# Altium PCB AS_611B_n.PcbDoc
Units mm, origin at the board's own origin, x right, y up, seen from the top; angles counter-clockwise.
Board outline 32 x 30 mm, 4 copper layers (Top Layer, Layer 1, Layer 2, Bottom Layer), stack 0.98 mm thick; 38 components, 30 nets, 225 pads, 183 vias.
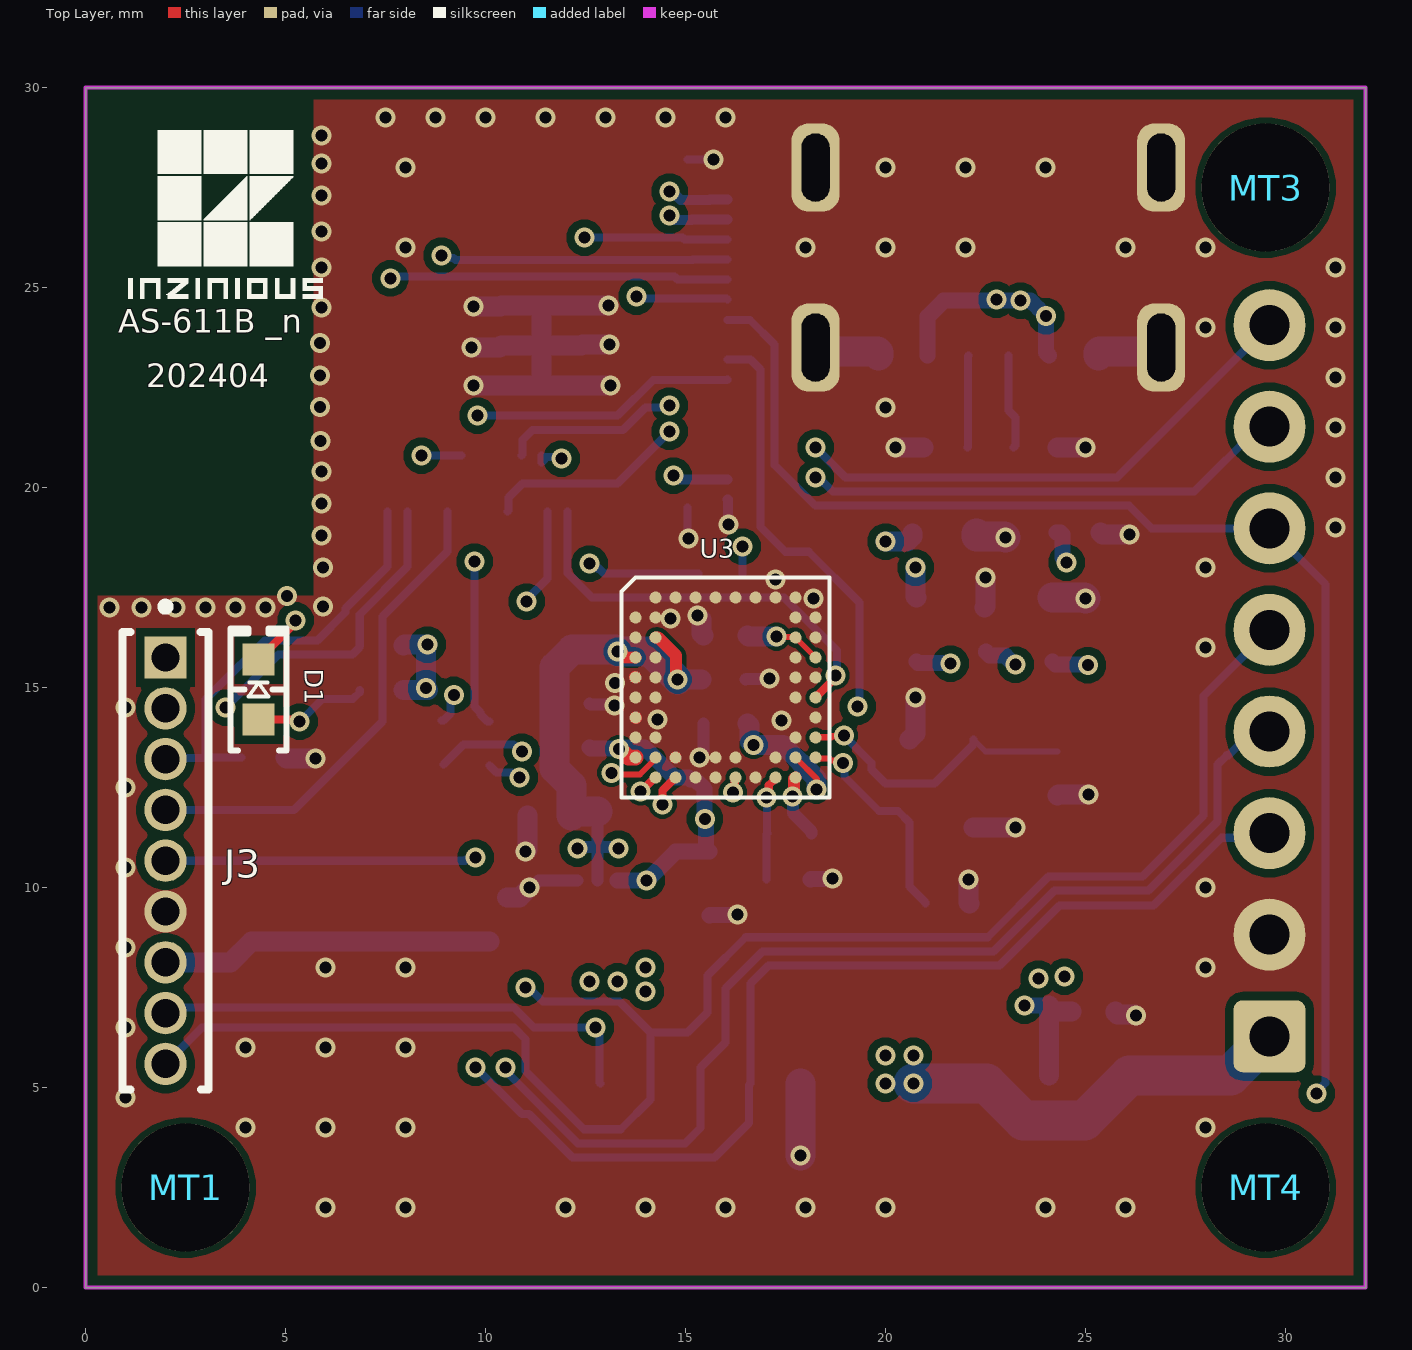
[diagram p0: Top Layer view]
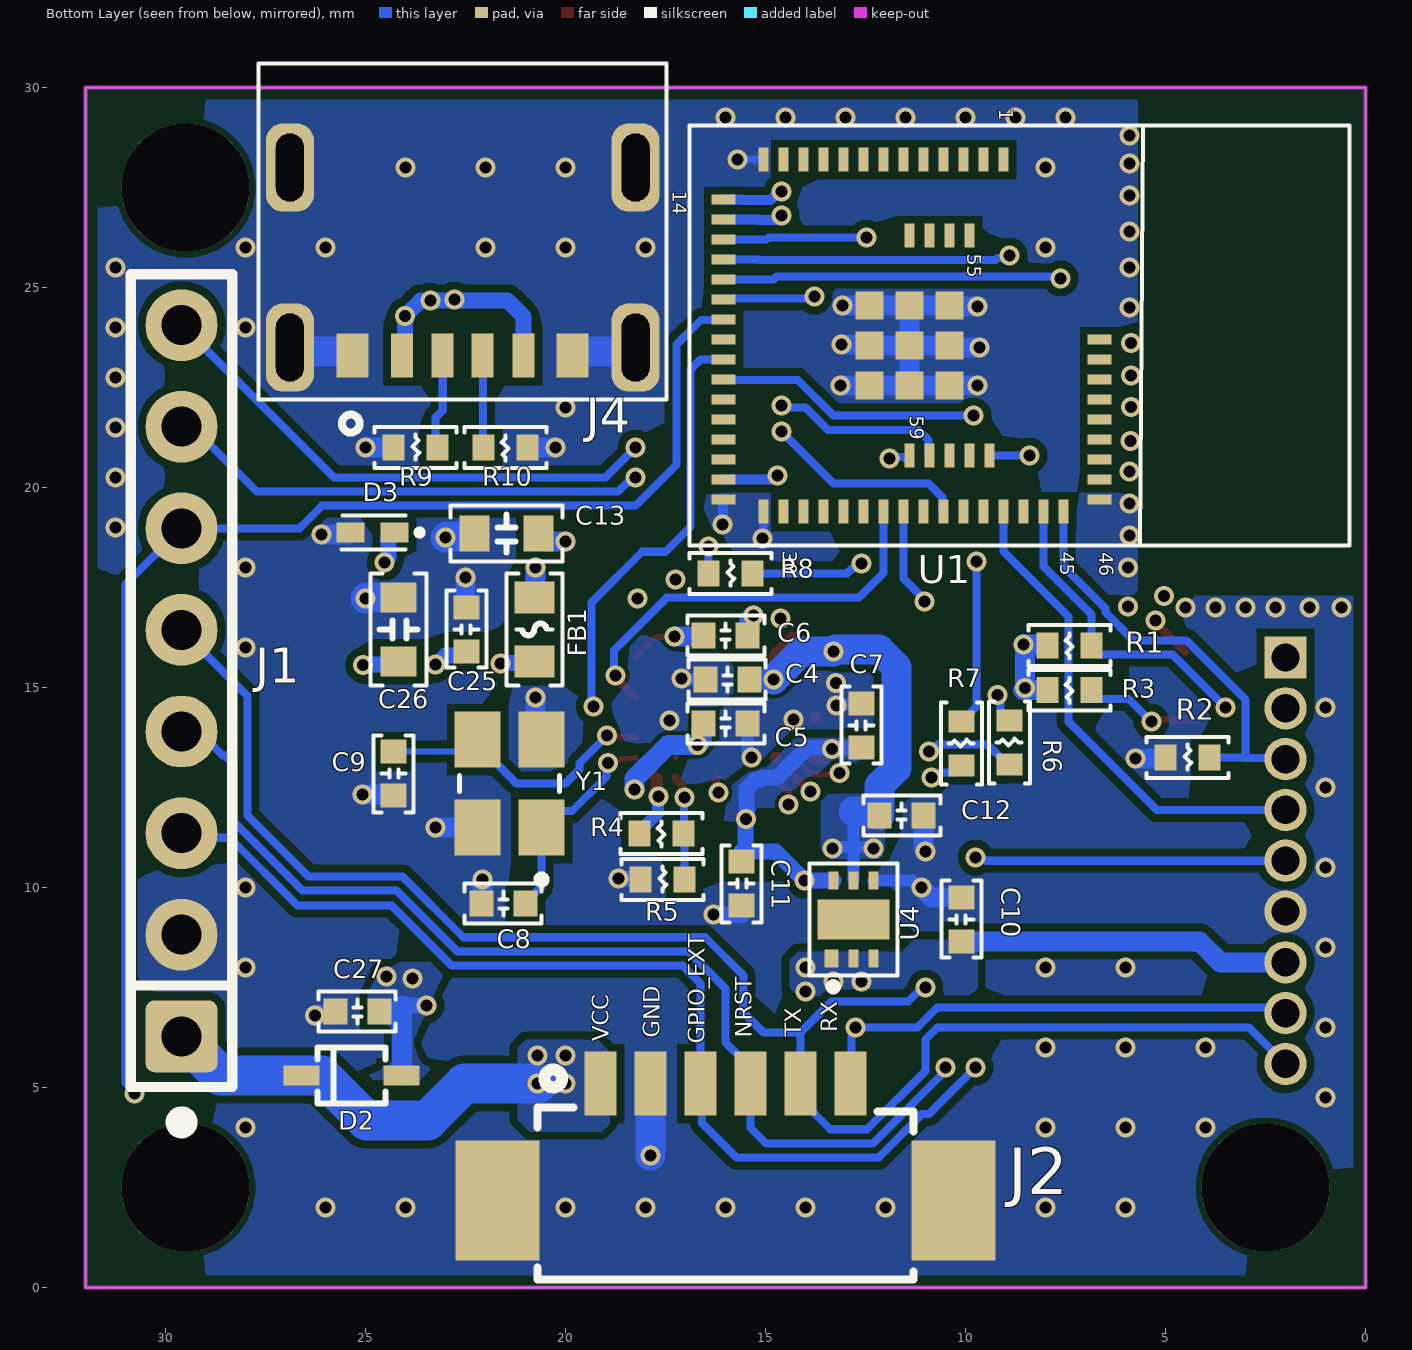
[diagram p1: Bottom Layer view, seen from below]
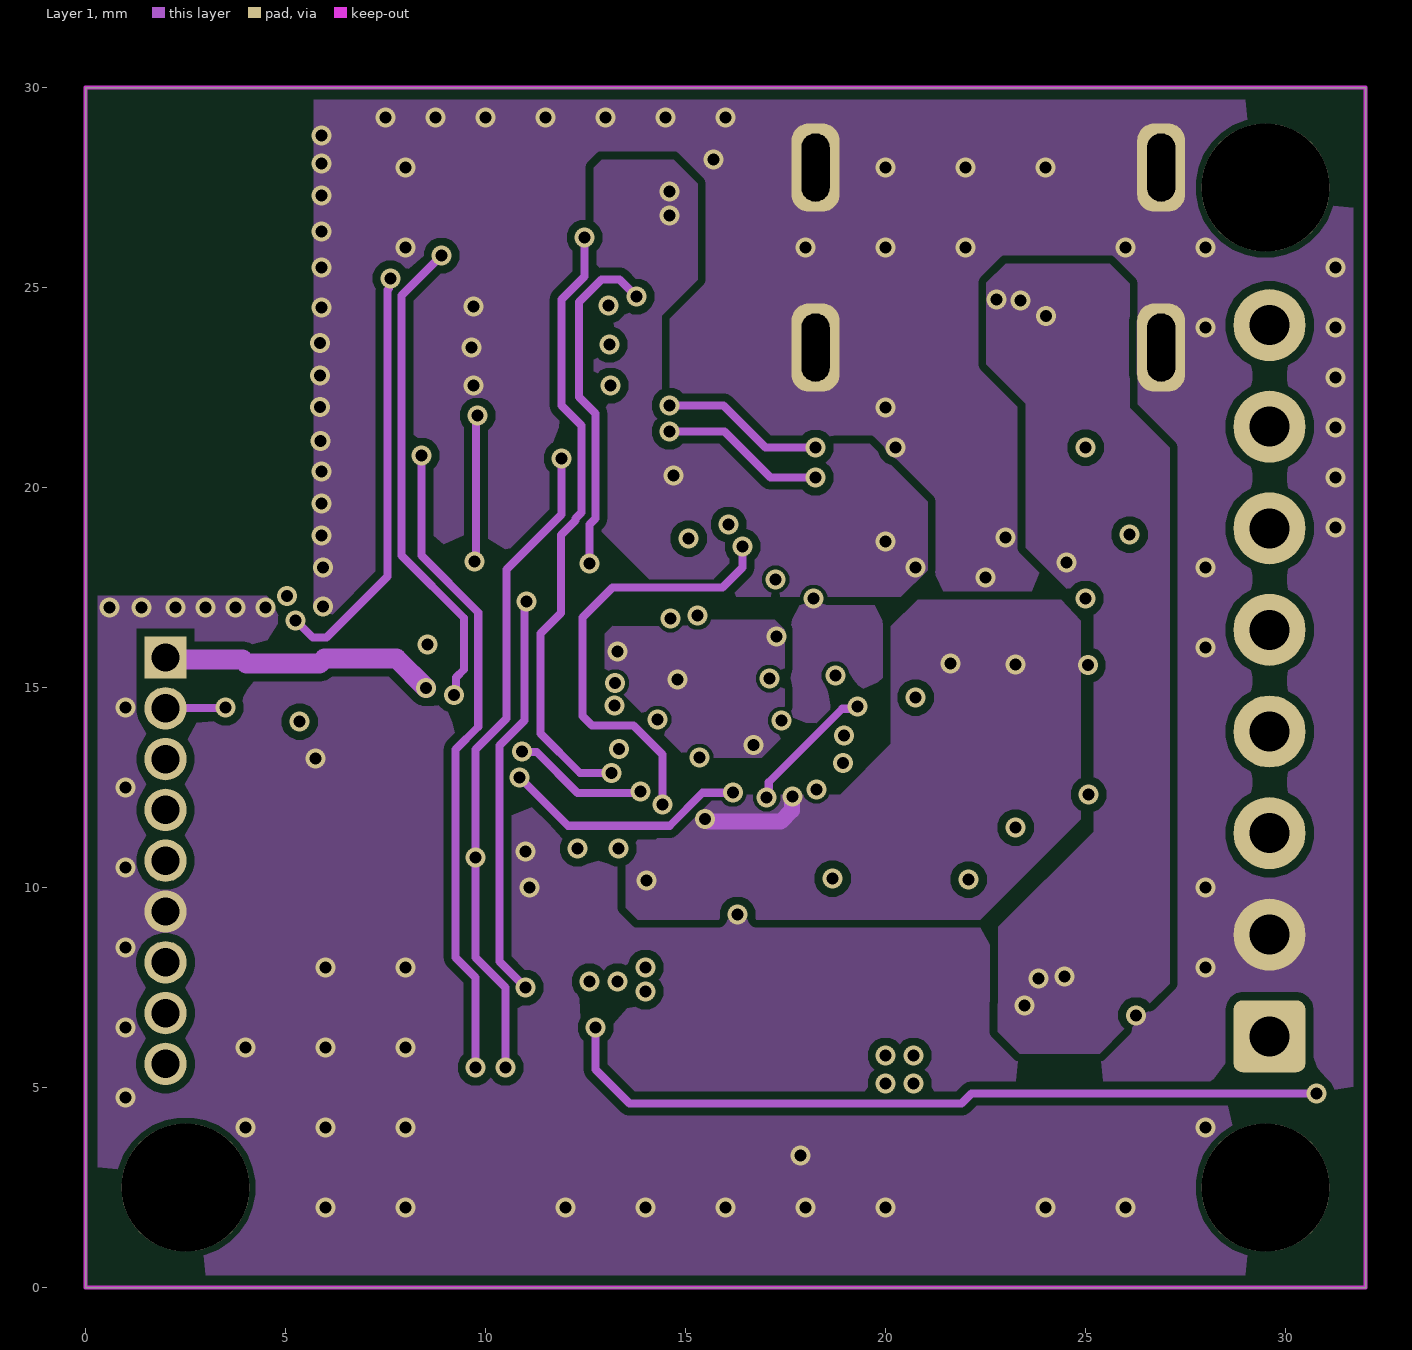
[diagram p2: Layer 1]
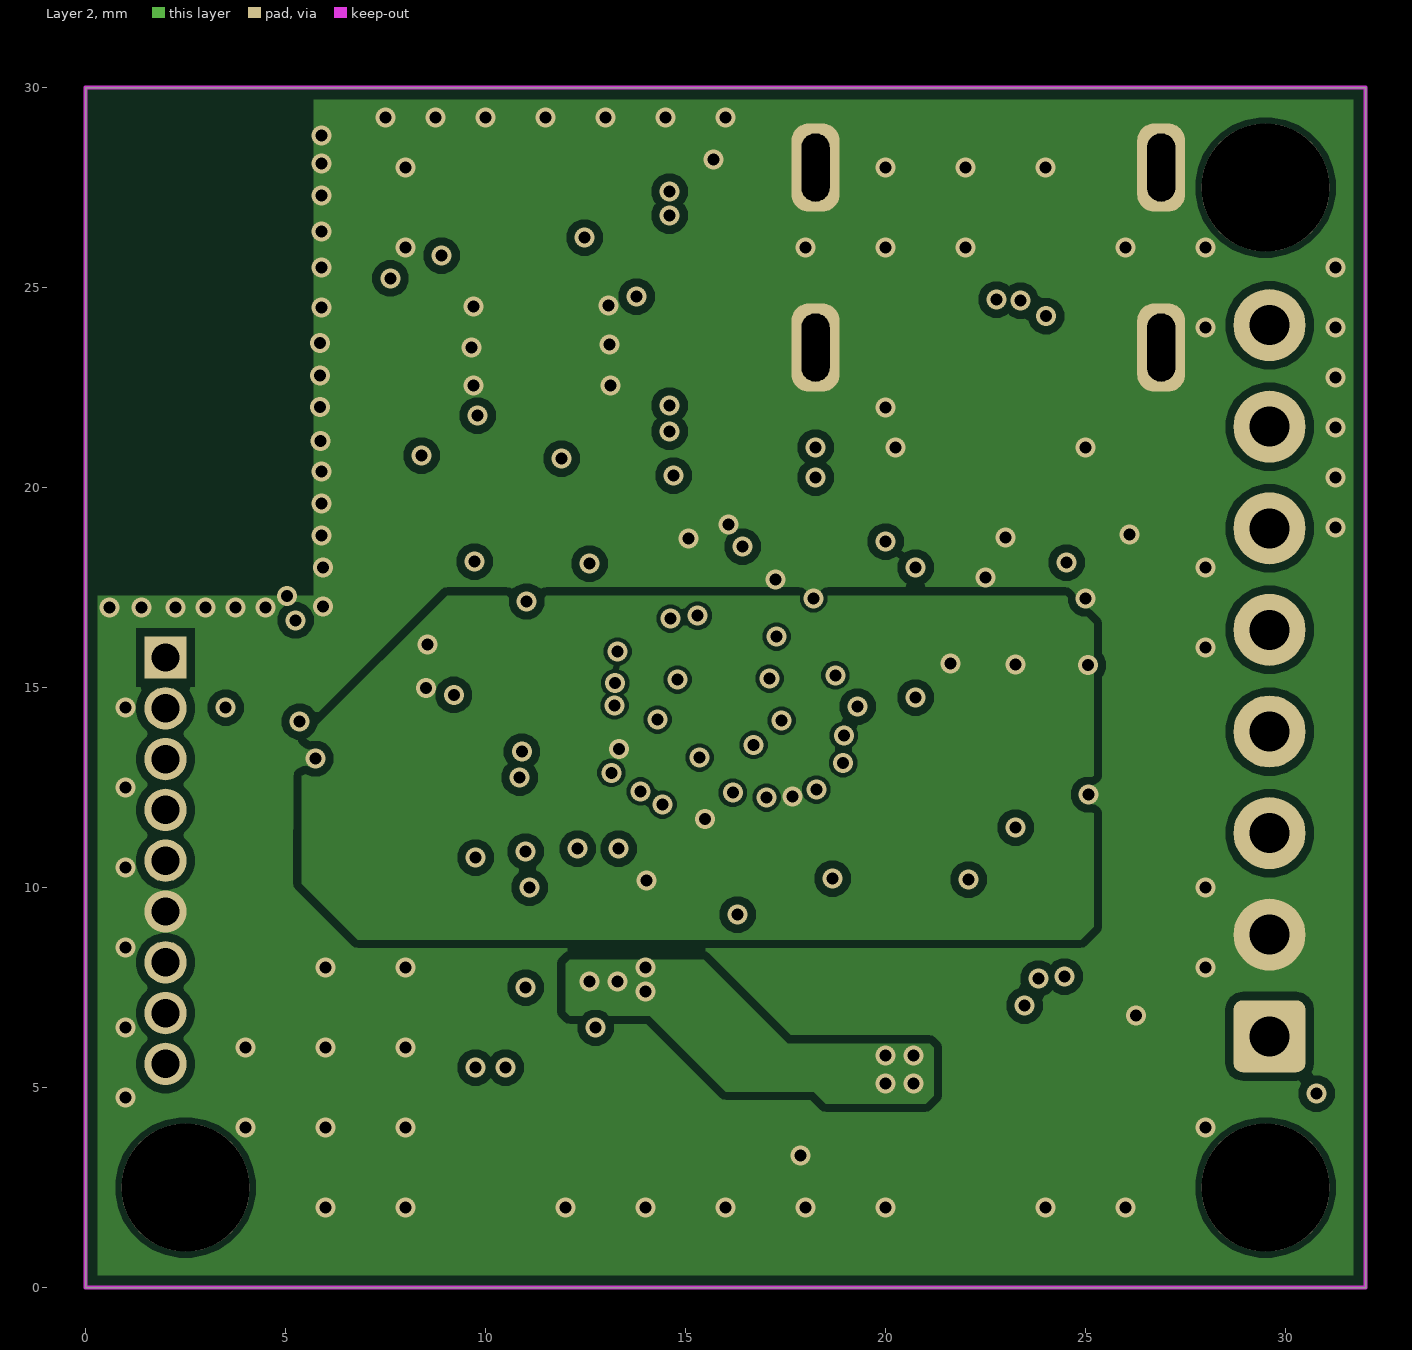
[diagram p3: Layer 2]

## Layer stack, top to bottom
Top Solder: solder mask 0.0102, Solder Resist, Dk 3.5
Top Layer: signal copper 0.0356
Dielectric 2: prepreg 0.0711, PP-006, Dk 4.1
Layer 1: signal copper 0.035
Dielectric 1: dielectric 0.697, FR-4, Dk 4.8
Layer 2: signal copper 0.035
Dielectric 3: prepreg 0.0711, PP-006, Dk 4.1
Bottom Layer: signal copper 0.0356
Bottom Solder: solder mask 0.0102, Solder Resist, Dk 3.5

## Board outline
0,0 0,30 32,30 32,0

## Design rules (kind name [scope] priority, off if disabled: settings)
AssemblyTestPointUsage [All] p1 off:
AssemblyTestpoint [All] p1 off: testpointundercomponent=TRUE minsize=1.016 maxsize=2.54 preferedsize=1.524 minholesize=0 maxholesize=1.016 preferedholesize=0.813 testpointgrid=0.025 usegrid=TRUE gridtolerance=0 allowsidetop=TRUE allowsidebottom=TRUE
BoardOutlineClearance BoardOutlineClearance_1 [OnLayer('Layer 2')] p1 off: gap=0.7 ignorepadtopadclearanceinfootprint=FALSE
BoardOutlineClearance [All] p2: gap=0.3 ignorepadtopadclearanceinfootprint=FALSE
Clearance Clearance_BGA [WithinRoom('BGA')] p1: gap=0.1 ignorepadtopadclearanceinfootprint=TRUE
Clearance [All] p2: gap=0.15 ignorepadtopadclearanceinfootprint=TRUE except(0.2: Arc-Fill Arc-Poly Arc-Region Track-Fill Track-Poly Track-Region SMDPad-Fill SMDPad-Poly SMDPad-Region THPad-Fill THPad-Poly THPad-Region Via-Fill Via-Poly Via-Region Fill-Fill Fill-Poly Fill-Region Poly-Poly Poly-Region Region-Region)
ComponentClearance [All] p1 off: gap=0.254 collisioncheckmode=3 verticalgap=0.254 showdistances=FALSE
DiffPairsRouting [All] p1: maxlimit=0.254 minlimit=0.1 mostfreqgap=0.1 toplayer_minwidth=0.17 toplayer_maxwidth=0.381 toplayer_prefwidth=0.17 midlayer1_minwidth=0.17 midlayer1_maxwidth=0.381 midlayer1_prefwidth=0.17 midlayer2_minwidth=0.17 midlayer2_maxwidth=0.381 midlayer2_prefwidth=0.17 bottomlayer_minwidth=0.17 bottomlayer_maxwidth=0.381 bottomlayer_prefwidth=0.17 maxuncoupledlength=12.7
FabricationTestPointUsage [All] p1 off: valid=0 allowmultiple=FALSE
FabricationTestpoint [All] p1 off: side=3 testpointundercomponent=TRUE minsize=1.016 maxsize=2.54 preferedsize=1.524 minholesize=0 maxholesize=1.016 preferedholesize=0.813 testpointgrid=0.025 allowsidetop=TRUE allowsidebottom=TRUE usegrid=TRUE gridtolerance=0
Height [All] p1 off: minheight=0 maxheight=25.4 prefheight=12.7
HoleSize [All] p1 off: absolutevalues=TRUE maxlimit=2.54 minlimit=0.025 maxpercent=80.000 minpercent=20.000
HoleToHoleClearance [All] p1 off: gap=0.254 allowstackedmicrovias=TRUE
LayerPairs [All] p1 off: enforce=TRUE
MinimumSolderMaskSliver [All] p1 off: minsoldermaskwidth=0.254
NetAntennae [All] p1 off: netantennaetolerance=0
PolygonConnect [All] p1: connectstyle=Direct reliefconductorwidth=0.254 reliefentries=4 polygonreliefangle="90 Angle" airgapwidth=0.254
RoomDefinition BGA [False] p1: confinementstyle=ConfineIn formatcopy=TRUE lockcomponents=FALSE outline 12.981,17.845 19,17.845 19,11.968 12.981,11.968
RoutingVias [All] p1: holewidth=0.711 width=1.27 viastyle="Through Hole" minholewidth=0.711 minwidth=1.27 maxholewidth=0.711 maxwidth=1.27 useviatemplates=TRUE viatemplateguid#1={830B9830-3F13-4738-AC1B-C66D827C6D3A} viatemplatename#1=v50h30m0mx0
SilkToSilkClearance [All] p1 off: silktosilkclearance=0.254
SilkToSolderMaskClearance [IsPad] p1 off: minsilkscreentomaskgap=0.254 clearancetoexposedcopper=TRUE
SolderMaskExpansion [All] p1: expansion=0.102 istentingtop=FALSE
Width [All] p1: maxlimit=3 minlimit=0.15 preferedwidth=0.15
16 further rules are at their usual default settings.

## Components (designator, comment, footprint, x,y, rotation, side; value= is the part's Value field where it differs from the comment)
C4 "1uF" "CAP 0402/1005" 15.95,15.2 r0 bottom
C5 "1uF" "CAP 0402/1005" 16,14.1 r180 bottom
C6 "1uF" "CAP 0402/1005" 16,16.3 r180 bottom
C7 "1uF" "CAP 0402/1005" 12.6,14.05 r90 bottom
C8 "8pF" "CAP 0402/1005" 21.55,9.6 r0 bottom
C9 "8pF" "CAP 0402/1005" 24.3,12.85 r270 bottom
C10 "CAP NP" "CAP 0402/1005" 10.1,9.2 r90 bottom value=1uF
C11 "CAP NP" "CAP 0402/1005" 15.6,10.1 r270 bottom value=1uF
C12 "CAP NP" "CAP 0402/1005" 11.6,11.8 r180 bottom value=1uF
C13 "4.7uF/6.3V/X5R" "CAP 0603/1608" 21.475,18.85 r0 bottom
C25 "0.1uF" "CAP 0402/1005" 22.475,16.45 r90 bottom
C26 "10uF/10V/X7R" "CAP 0603/1608" 24.175,16.45 r270 bottom
C27 "CAP NP" "CAP 0402/1005" 25.2,6.9 r0 bottom value=1uF
D1 "GREEN" "LED 0603/1608 RED -21" 4.325,14.95 r90 top
D2 "DIODE_POWER_0" "SOD-323 - 21" 25.35,5.3 r0 bottom value=BAT760-7
D3 "DIODE BI-DIR TRIG" SOD523 24.825,18.875 r180 bottom value=LESD5D5.0CT1G
FB1 "BLM18AG121SN1D" "FER 0603/1608" 20.775,16.45 r270 bottom
J1 "EXT_IO1/2.54mm" "Pin Header 1x8 TH Pitch 2.54mm" 29.6,6.28 r90 bottom locked
J2 "EXT_IO2/12505wr-06" 12505WR-06/53261-0671 16,5.1 r180 bottom locked
J3 "Debug/1.27mm" "PIN HEADER 1X9 TH 1.27mm" 2,10.671 r270 top
J4 "TYPE-C-31-M-17" CON/USB-C/6P-1 22.57,23.5 r0 bottom locked
MT1 "MOUNT HOLE" "MT-3 /HOLE" 2.5,2.5 r0 top locked
MT3 "MOUNT HOLE" "MT-3 /HOLE" 29.5,27.5 r0 top locked
MT4 "MOUNT HOLE" "MT-3 /HOLE" 29.5,2.5 r0 top locked
R1 "RESISTOR/SM" "RES 0402/1005" 7.4,16.05 r180 bottom value=10K
R2 "RESISTOR/SM" "RES 0402/1005" 4.45,13.25 r0 bottom value=10K
R3 "220R" "RES 0402/1005" 7.405,14.933 r180 bottom
R4 "DNI" "RES 0402/1005" 17.6,11.35 r180 bottom
R5 "DNI" "RES 0402/1005" 17.575,10.2 r0 bottom
R6 "33R" "RES 0402/1005" 8.9,13.625 r270 bottom
R7 "33R" "RES 0402/1005" 10.1,13.6 r270 bottom
R8 "33R" "RES 0402/1005" 15.875,17.85 r0 bottom
R9 "5.1K" "RES 0402/1005" 23.75,21 r0 bottom
R10 "5.1K" "RES 0402/1005" 21.5,21 r180 bottom
U1 "NU-BW4001" nu40 11.4,23.55 r270 bottom locked value=nRF52840-QIAA
U3 "A121" A111 16,15 r0 top locked
U4 "VRD1833MLX" "LLP-6 / L2.0-W1.8-P0.50-BL-EP" 12.825,9.2 r180 bottom
Y1 "24MHz" XTAL_3225 21.4,12.6 r90 bottom

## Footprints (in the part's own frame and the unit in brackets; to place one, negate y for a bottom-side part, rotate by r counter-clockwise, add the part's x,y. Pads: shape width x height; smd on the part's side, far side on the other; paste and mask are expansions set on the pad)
12505WR-06/53261-0671 [mm]
  rect 0.8x1.6 smd: 1(-3.125,0) 2(-1.875,0) 3(-0.625,0) 4(0.625,0) 5(1.875,0) 6(3.125,0)
  rect 2.1x3 smd: H(-5.7,-2.925) H(5.7,-2.925)
  silkscreen extent -4.7,-4.9 4.7,0.35, body extent -6.39,-4.75 6.26,0.45, height 3.4
A111 [mm]
  round 0.3 smd: A2(-1.75,2.25) A3(-1.25,2.25) A4(-0.75,2.25) A5(-0.25,2.25) A6(0.25,2.25) A7(0.75,2.25) A8(1.25,2.25) A9(1.75,2.25) B1(-2.25,1.75) B2(-1.75,1.75) B9(1.75,1.75) B10(2.25,1.75) C1(-2.25,1.25) C2(-1.75,1.25) C9(1.75,1.25) C10(2.25,1.25) D1(-2.25,0.75) D2(-1.75,0.75) D9(1.75,0.75) D10(2.25,0.75) E1(-2.25,0.25) E2(-1.75,0.25) E9(1.75,0.25) E10(2.25,0.25) F1(-2.25,-0.25) F2(-1.75,-0.25) F9(1.75,-0.25) F10(2.25,-0.25) G1(-2.25,-0.75) G10(2.25,-0.75) H1(-2.25,-1.25) H2(-1.75,-1.25) H9(1.75,-1.25) H10(2.25,-1.25) J1(-2.25,-1.75) J2(-1.75,-1.75) J3(-1.25,-1.75) J5(-0.25,-1.75) J6(0.25,-1.75) J8(1.25,-1.75) J9(1.75,-1.75) J10(2.25,-1.75) K2(-1.75,-2.25) K3(-1.25,-2.25) K4(-0.75,-2.25) K5(-0.25,-2.25) K6(0.25,-2.25) K7(0.75,-2.25) K8(1.25,-2.25) K9(1.75,-2.25)
  silkscreen extent -2.6,-2.75 2.6,2.75, body extent -2.61,-2.75 2.63,2.75, height 0.9
"CAP 0402/1005" [mm] "Chip Capacitor, 2-Leads, Body 1.02x0.51mm, IPC Medium Density"
  rect 0.6x0.65 smd: 1(-0.55,0) 2(0.55,0)
  silkscreen extent -0.95,-0.5 0.97,0.5, body extent -0.5,-0.26 0.5,0.26, height 0.52
"CAP 0603/1608" [mm] "Chip Capacitor, 2-Leads, Body 1.60x0.80mm, IPC Medium Density"
  rect 0.75x0.9 smd: 1(-0.8,0) 2(0.8,0)
  silkscreen extent -1.4,-0.7 1.4,0.7, body extent -0.8,-0.41 0.8,0.41, height 0.82
CON/USB-C/6P-1 [mm]
  rect 0.55x1.1 smd: A5(-0.5,0.2) A9(1.52,0.2) B5(0.5,0.2) B9(-1.52,0.2)
  rect 0.8x1.1 smd: A12(2.75,0.2) B12(-2.75,0.2)
  rrect70% 1.2x2.2 hole 0.7 slot 1.7 at 90 deg: MP(-4.32,-4.5) MP(-4.32,0) MP(4.32,-4.5) MP(4.32,0)
  silkscreen extent -5.1,-7.1 5.1,2.12, body extent -4.47,-6.7 4.47,0.2, height 3.26
"FER 0603/1608" [mm] "Chip Ferrite, 2-Leads, Body 1.60x0.80mm, IPC Medium Density"
  rect 0.8x1 smd: 1(-0.8,0) 2(0.8,0)
  silkscreen extent -1.4,-0.7 1.4,0.7, body extent -0.8,-0.41 0.8,0.41, height 0.82
"LED 0603/1608 RED -21" [mm] "Chip Diode, 2-Leads, Body 1.60x0.80mm, IPC Medium Density"
  rect 0.8x0.8 smd: 1(0.75,0) 2(-0.75,0)
  silkscreen extent -1.52,-0.7 1.52,0.7, body extent -0.8,-0.4 0.8,0.4, height 0.53
"LLP-6 / L2.0-W1.8-P0.50-BL-EP" [mm]
  rect 0.35x0.45 smd paste+0 mask+0.051: 1(-0.525,-0.975)
  rect 0.25x0.45 smd paste+0 mask+0.051: 2(0.025,-0.975) 3(0.525,-0.975) 4(0.525,0.975) 5(0.025,0.975) 6(-0.475,0.975)
  rect 1.8x1 smd paste+0 mask+0.051: 7(0.025,0)
  silkscreen extent -1.07,-1.74 1.12,1.4, body extent -0.9,-1 0.9,1, height 0.6
"MT-3 /HOLE" [mm] "Mount Hole 4mm"
  round 3.2 hole 3.2 unplated mask+0: 1(0,0)
nu40 [mm]
  rect 0.6x0.25 smd mask+0.05: 1(-4.65,2.35) 2(-4.65,1.85) 3(-4.65,1.35) 4(-4.65,0.85) 5(-4.65,0.35) 6(-4.65,-0.15) 7(-4.65,-0.65) 8(-4.65,-1.15) 9(-4.65,-1.65) 10(-4.65,-2.15) 11(-4.65,-2.65) 12(-4.65,-3.15) 13(-4.65,-3.65) 30(4.15,-3.65) 31(4.15,-3.15) 32(4.15,-2.65) 33(4.15,-2.15) 34(4.15,-1.65) 35(4.15,-1.15) 36(4.15,-0.65) 37(4.15,-0.15) 38(4.15,0.35) 39(4.15,0.85) 40(4.15,1.35) 41(4.15,1.85) 42(4.15,2.35) 43(4.15,2.85) 44(4.15,3.35) 45(4.15,3.85) 55(-2.75,1.5) 56(-2.75,1) 57(-2.75,0.5) 58(-2.75,0) 59(2.75,0) 60(2.75,0.5) 61(2.75,1) 62(2.75,1.5) 63(2.75,2)
  rect 0.25x0.6 smd mask+0.05: 14(-3.65,-4.65) 15(-3.15,-4.65) 16(-2.65,-4.65) 17(-2.15,-4.65) 18(-1.65,-4.65) 19(-1.15,-4.65) 20(-0.65,-4.65) 21(-0.15,-4.65) 22(0.35,-4.65) 23(0.85,-4.65) 24(1.35,-4.65) 25(1.85,-4.65) 26(2.35,-4.65) 27(2.85,-4.65) 28(3.35,-4.65) 29(3.85,-4.65) 46(3.85,4.75) 47(3.35,4.75) 48(2.85,4.75) 49(2.35,4.75) 50(1.85,4.75) 51(1.35,4.75) 52(0.85,4.75) 53(0.35,4.75) 54(-0.15,4.75)
  rect 0.7x0.7 smd paste-2539.97 mask+0: 64(-1,1) 65(0,1) 66(1,1) 67(-1,0) 68(0,0) 69(1,0) 70(-1,-1) 71(0,-1) 72(1,-1)
  silkscreen extent -5.5,-5.5 5,11, body extent -5.51,-5.5 5,11.01, height 2.4
"Pin Header 1x8 TH Pitch 2.54mm" [mm] "PinHeader 1x8 TH Pitch 2.54mm"
  rrect25% 1.8x1.8 hole 1: 1(0,0)
  round 1.8 hole 1: 2(2.54,0) 3(5.08,0) 4(7.62,0) 5(10.16,0) 6(12.7,0) 7(15.24,0) 8(17.78,0)
  silkscreen extent -2.3,-1.27 19.05,1.27, body extent -1.27,-1.27 19.05,1.27, height 9.5
"PIN HEADER 1X9 TH 1.27mm" [mm]
  rect 1.06x1.06 hole 0.71: 1(-5.08,0)
  round 1.06 hole 0.71: 2(-3.81,0) 3(-2.54,0) 4(-1.27,0) 5(0,0) 6(1.27,0) 7(2.54,0) 8(3.81,0) 9(5.08,0)
  silkscreen extent -6.45,-1.08 5.71,1.08, body extent -5.71,-1.08 5.71,1.08, height 3.91
"RES 0402/1005" [mm] "Chip Resistor, 2-Leads, Body 1.0x0.5mm, IPC Medium Density"
  rect 0.55x0.65 smd: 1(-0.55,0) 2(0.55,0)
  silkscreen extent -1.02,-0.51 1.02,0.51, body extent -0.5,-0.25 0.5,0.25, height 0.35
SOD523 [mm]
  rect 0.7x0.5 smd: 1(0.55,0) 2(-0.55,0)
  silkscreen extent -0.77,-0.43 1.22,0.43, body extent -0.77,-0.4 0.83,0.4, height 0.65
"SOD-323 - 21" [mm]
  rect 0.9x0.5 smd: 1(1.25,0) 2(-1.25,0)
  silkscreen extent -0.85,-0.7 0.85,0.7, body extent -1.34,-0.66 1.34,0.64, height 1.15
XTAL_3225 [mm]
  rect 1.4x1.15 smd: 1(-1.1,-0.8) 2(1.1,-0.8) 3(1.1,0.8) 4(-1.1,0.8)
  silkscreen extent -2.5,-1.25 0.2,1.25, body extent -1.6,-1.25 1.6,1.25, height 1

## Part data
C4 C5 C6 C7 C8 C9: library part "CAP NP"
C13 C25: library part C0603-4µ7-6.3V-X7R, "Capacitor, X7R, ±10%"
C26: library part Cap, "MLCC"
D1: library part LED
FB1: library part FB0402-120R@100M-500mA, "Ferrite Bead, 120 Ohm @ 100MHz, 500mA, 250 mOhm Max", Manufacturer=Murata, Manufacturer Part Number=BLM15AG121SN1D, Part number IPS=00000009954, Supplier Part Number 1=490-1005-1-ND
J1: library part "HEADER 8"
J2: library part "HEADER 6"
J3: library part "Header 9", "Header, 9-Pin"
J4: library part CON/USB-C/6P, "6P C-type Connector"
MT1 MT3 MT4: library part "Mount Bolt"
R3 R4 R5 R6 R7 R8 R9 R10: library part RESISTOR/SM
U1: library part nu40_1, "BLE Module", Manufacturer="Nordic Semiconductor", Manufacturer Part Number=nRF52840-QIAAF0, Part number IPS=N.A.
Y1: library part CRYSTAL13

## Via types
v1: diameter 0.5, hole 0.3, Top Layer to Bottom Layer, tented both sides, 183 vias

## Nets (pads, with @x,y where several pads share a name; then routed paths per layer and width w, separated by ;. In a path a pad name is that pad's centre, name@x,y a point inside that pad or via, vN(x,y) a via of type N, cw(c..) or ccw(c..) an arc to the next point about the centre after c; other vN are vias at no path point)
ENABLE: U1.36 U3.F10 | length 10.5
  Top Layer w0.203: U3.F10 18.25,14.753 18.747,15.25 v1(18.747,15.305)
  Bottom Layer w0.203: U1.36 12.05,17.864 12.664,17.25 17.466,17.25 18.788,15.927 18.788,15.347 v1(18.747,15.305)
GND: C4.2 C5.2 C6.2 C7.2 C8.2 C9.2 C10.2 C11.2 C12.2 C13.2 C25.2 C26.1 C27.2 D3.2 J1.2 J2.2 J2.H J3.6 J4.A12 J4.B12 J4.MP R2.2 R5.2 R9.2 R10.2 U1.13 U1.29 U1.30 U1.46 U1.64 U1.65 U1.66 U1.67 U1.68 U1.69 U1.70 U1.71 U1.72 U3.A2 U3.A3 U3.A4 U3.A5 U3.A6 U3.A7 U3.A8 U3.A9 U3.B1 U3.B2 U3.B9 U3.B10 U3.C1 U3.C10 U3.D2 U3.D9 U3.E1 U3.E2 U3.E9 U3.E10 U3.F1 U3.F2 U3.F9 U3.G1 U3.G10 U3.H1 U3.H2 U3.H9 U3.J3 U3.J5 U3.J6 U3.J8 U3.K4 U3.K5 U3.K7 U4.4 Y1.2 Y1.4 | length 36.2
  Top Layer w0.3: v1(13.242,15.11) v1@13.262,15.11 ; U3.E1@13.738,15.262 U3.E1 ; U3.G1 U3.G1@13.762,14.238 ; v1@14.262,14.238 v1(14.3,14.2) ; v1@15.312,13.212 v1(15.35,13.25) ; v1(17.4,14.175) v1@17.438,14.137 ; v1(18.2,17.225) 18.2,17.171 v1@18.25,17.121
  Bottom Layer w0.2: U1.30@15.05,19.499 15.056,19.493 15.056,18.744 v1(15.075,18.725) ; U1.13 v1(15.7,28.2)
  Bottom Layer w0.25: U1.29 16.063,19.7 16.063,19.087 v1(16.076,19.074)
  Bottom Layer w0.3: v1(11.1,10) 11.154,10 11.329,10.175 U4.4 ; C7.2 12.624,14.576 13.201,14.576 v1(13.225,14.552) ; v1(15.35,13.25) 15.35,13.304 15.45,13.404 C5.2 ; C4.2 16.512,15.212 17.087,15.212 v1(17.1,15.225)
  Bottom Layer w0.4: C11.2@15.6,9.3 15.613,9.313 16.288,9.313 v1(16.3,9.325) ; R5.2 18.137,10.212 18.663,10.212 v1(18.675,10.225)
  Bottom Layer w0.5: R2.2 5.025,13.225 v1(5.75,13.225) ; v1(9.65,23.5) 10.35,23.5 U1.65 U1.68 ; v1(9.7,22.55) U1.66 U1.69 ; v1(9.7,24.525) 10.375,24.525 U1.64 U1.67 ; 10.543,9.75 10.75,9.75 10.85,9.75 v1(11.1,10) ; v1(11,10.9) 11.05,10.95 C12.2 ; v1(13.075,24.55) U1.70 U1.67 ; v1(13.1,23.575) 12.425,23.575 U1.71 U1.68 ; v1(13.125,22.55) U1.72 U1.69 ; v1(15.304,16.796) 15.4,16.7 15.4,16.35 C6.2 ; v1(20.25,21) R10.2 ; Y1.2 20.75,13.85 v1(20.75,14.75) ; v1(22.075,10.2) 22.075,9.625 C8.2 ; Y1.4 v1(23.25,11.5) ; C25.2 22.5,17.025 v1(22.5,17.75) ; C9.2 24.325,12.325 v1(25.075,12.325) ; R9.2 v1(25,21) ; D3.2 25.428,18.822 v1(26.102,18.822) ; C27.2 25.75,6.875 25.8,6.825 26.242,6.825 v1(26.26,6.807) ; U1.69 U1.68 ; U1.68 U1.67
  Bottom Layer w0.75: v1(17.875,3.3) J2.2 ; J4.MP@18.25,23.5 18.35,23.4 19.795,23.4 19.82,23.375 J4.B12 ; C13.2 22.275,18.775 22.975,18.775 v1(23,18.75) ; C26.1 24.975,17.25 v1(25,17.225) ; J4.A12 25.32,23.375 25.345,23.4 26.79,23.4 J4.MP@26.89,23.5
  other v1: 6,2 8,2 12,2 14,2 16,2 18,2 20,2 24,2 26,2 4,4 6,4 8,4 28,4 1,4.75 4,5.998 6,5.998 8,5.998 1,6.5 6,8 8,8 28,8 1,8.5 28,10 1,10.5 1,12.5 1,14.5 28,16 14.625,16.725 0.6,17 1.4,17 2.25,17 3,17 3.75,17 4.5,17 5.936,17.025 5.032,17.294 17.25,17.702 5.937,18.006 28,18 5.9,18.8 31.25,19 5.9,19.6 31.25,20.25 5.9,20.4 5.874,21.16 31.25,21.5 20,22 5.865,22.017 31.25,22.75 5.857,22.801 5.865,23.618 28,24 31.25,24 5.9,24.5 5.9,25.5 31.25,25.5 8,26 18,26 20,26 22,26 26,26 28,26 5.9,26.4 5.9,27.3 8,28 20,28 22,28 24,28 5.9,28.1 5.9,28.8 7.5,29.25 8.75,29.25 10,29.25 11.5,29.25 13,29.25 14.5,29.25 16,29.25
GPIO_EXT: J1.3 J2.3 U1.63 | length 43.5
  Layer 1 w0.203: v1(8.4,20.8) 8.4,18.297 9.819,16.879 9.819,14.018 9.248,13.448 9.248,8.253 9.75,7.751 v1(9.75,5.5)
  Bottom Layer w0.203: v1(8.4,20.8) U1.63 ; v1(9.75,5.5) 10.913,4.337 11.084,4.337 12.17,3.25 15.725,3.25 16.589,4.114 16.589,5.064 J2.3 16.625,7.6 17.075,8.05 22.849,8.05 24.349,9.55 26.7,9.55 28.395,11.245 29.485,11.245 J1.3
INTERRUPT: R4.2 R5.1 U1.22 U3.K8 | length 16.8
  Top Layer w0.203: v1(17.025,12.25) 17.082,12.307 17.082,12.556 17.25,12.724 U3.K8
  Layer 1 w0.203: v1(17.025,12.25) 17.082,12.307 17.082,12.632 18.918,14.468 19.243,14.468 v1(19.3,14.525)
  Bottom Layer w0.203: U1.22 16.625,23.2 16.873,22.952 16.873,19.021 17.5,18.394 18.081,18.394 19.348,17.127 19.348,14.573 v1(19.3,14.525) ; R5.1 17.025,11.325 R4.2 17.037,11.363 17.037,12.238 v1(17.025,12.25)
LED: D1.1 U1.18 | length 20.2
  Top Layer w0.2: D1.1@4.513,15.888 5.25,16.625 v1(5.25,16.681)
  Layer 1 w0.2: v1(5.25,16.681) 5.681,16.25 6.025,16.25 7.55,17.775 7.55,24.933 7.593,24.975 7.593,25.2 v1(7.621,25.229)
  Bottom Layer w0.2: v1(7.621,25.229) 7.668,25.275 14.725,25.275 14.8,25.2 U1.18
NetC8_1: C8.1 U3.J10 Y1.1 | length 5.4
  Top Layer w0.152: U3.J10 18.275,13.225 18.6,13.225 18.649,13.177 18.874,13.177 v1(18.941,13.11)
  Bottom Layer w0.2: v1(18.941,13.11) 18.979,13.072 18.979,12.771 19.842,11.908 20.317,11.908 20.6,11.625 20.6,10.025 21,9.625 C8.1
NetC9_1: C9.1 U3.H10 Y1.3 | length 7.3
  Top Layer w0.152: U3.H10 18.258,13.758 18.642,13.758 18.667,13.783 18.942,13.783 v1(18.959,13.799)
  Bottom Layer w0.152: Y1.3 22.5,13.4 C9.1
  Bottom Layer w0.2: v1(18.959,13.799) 19.65,13.108 19.65,12.95 20,12.6 21.225,12.6 22.2,13.575 Y1.3
NetC27_1: C27.1 D2.2 D3.1 J4.A9 J4.B9 | length 9
  Bottom Layer w0.4: J4.B9 21.05,24.275 21.45,24.675 23.625,24.675 23.824,24.476 v1(24.015,24.285) 24.015,23.375 J4.A9 ; v1(23.475,7.05) 24.1,7.05 ; D3.1 24.375,18.875 24.425,18.825 24.425,18.252 24.525,18.152 v1(24.525,18.125)
  Bottom Layer w0.5: D2.2@24.085,5.3 24.085,7.05 ; 24.189,6.9 C27.1
  other v1: 23.825,7.725 24.475,7.775 23.375,24.675 22.775,24.7
NetD1_2: D1.2 R3.2 | length 2.9
  Top Layer w0.203: D1.2 5.3,14.2 v1(5.355,14.145)
  Bottom Layer w0.203: v1(5.355,14.145) 5.919,14.71 6.682,14.71 6.855,14.883 R3.2
NetJ4_A5: J4.A5 R10.1 | length 2.3
  Bottom Layer w0.203: R10.1 22.06,21.01 22.06,23.29 J4.A5
NetJ4_B5: J4.B5 R9.1 | length 2.4
  Bottom Layer w0.203: J4.B5 23.07,21.93 23.25,21.75 23.25,21.05 R9.1
NetR6_2: R6.2 U3.K2 | length 6.2
  Top Layer w0.203: v1(13.875,12.402) 13.888,12.402 14.237,12.75 U3.K2
  Layer 1 w0.203: v1(10.907,13.398) 10.917,13.388 11.28,13.388 12.302,12.366 12.908,12.366 13.839,12.366 v1(13.875,12.402)
  Bottom Layer w0.203: R6.2@8.95,13.075 9.452,13.577 10.698,13.577 10.877,13.398 v1(10.907,13.398)
NetR7_2: R7.2 U3.K6 | length 7.5
  Top Layer w0.203: v1(16.181,12.369) 16.231,12.42 16.231,12.731 U3.K6
  Layer 1 w0.203: v1(10.855,12.75) 12.059,11.545 14.605,11.545 15.429,12.369 v1(16.181,12.369)
  Bottom Layer w0.2: R7.2 10.275,12.875 10.649,12.875 10.774,12.75 v1(10.855,12.75)
NetR8_2: R8.2 U3.K3 | length 12.6
  Top Layer w0.203: v1(14.425,12.075) 14.425,12.425 U3.K3
  Layer 1 w0.203: v1(14.425,12.075) 14.425,13.325 13.7,14.05 12.659,14.05 12.425,14.284 12.425,16.75 13.175,17.5 15.925,17.5 16.425,18 v1(16.425,18.525)
  Bottom Layer w0.203: R8.2 v1(16.425,18.525)
NRST: J1.4 J2.4 J3.5 U1.59 | length 51.7
  Layer 1 w0.203: v1(10.5,5.5) 10.5,7.501 9.75,8.251 v1(9.75,10.75) 9.75,13.45 10.525,14.225 10.525,17.95 11.9,19.325 v1(11.9,20.725)
  Bottom Layer w0.203: J3.5 9.483,10.671 9.505,10.693 9.693,10.693 v1(9.75,10.75) ; v1(10.5,5.5) 10.5,5.42 12.316,3.603 14.983,3.603 15.375,3.995 15.375,5.5 16,6.125 16,7.474 16.929,8.403 22.703,8.403 24.223,9.923 26.573,9.923 28.3,11.651 28.3,13.075 28.532,13.307 28.575,13.307 29.168,13.9 J1.4 ; U1.59 11.4,20.625 U1.59@11.488,20.713 ; U1.59@11.402,20.798 11.402,20.784 11.423,20.762 11.863,20.762 v1(11.9,20.725)
SPI_CLK: R6.1 U1.17 | length 20.2
  Layer 1 w0.2: v1(8.9,25.8) 7.9,24.8 7.9,18.3 9.467,16.733 9.467,15.456 9.263,15.252 9.263,14.871 v1(9.206,14.814)
  Bottom Layer w0.2: R6.1 8.95,14.175 9.125,14.35 9.125,14.652 9.206,14.732 v1(9.206,14.814) ; v1(8.9,25.8) 8.957,25.743 9.196,25.743 9.246,25.693 15.175,25.693 15.182,25.7 U1.17
SPI_MISO: R8.1 U1.19 | length 13.8
  Layer 1 w0.203: v1(12.6,18.1) 12.6,19.078 12.752,19.229 12.752,21.848 12.336,22.264 12.336,24.639 12.897,25.2 13.35,25.2 v1(13.775,24.775)
  Bottom Layer w0.203: v1(12.6,18.1) 12.68,18.1 12.813,17.968 12.846,17.968 12.964,17.85 R8.1 ; v1(13.775,24.775) 13.827,24.723 16.027,24.723 U1.19
SPI_MOSI: R7.1 U1.23 | length 14.5
  Layer 1 w0.203: v1(9.725,18.15) 9.763,18.187 9.763,21.762 v1(9.8,21.8)
  Bottom Layer w0.203: v1(9.725,18.15) 9.725,14.525 9.877,14.373 9.877,14.323 10.05,14.15 R7.1 ; v1(9.8,21.8) 13.301,21.8 14.193,22.693 16.043,22.693 U1.23
SPI_SS: U1.16 U3.J2 | length 20.4
  Top Layer w0.15: v1(13.147,12.867) 13.187,12.827 13.857,12.827 14.25,13.22 U3.J2
  Layer 1 w0.2: v1(12.475,26.25) 12.475,25.275 11.9,24.7 11.9,22.05 12.4,21.55 12.4,19.375 12.248,19.223 12.248,19.176 11.887,18.814 11.887,16.86 11.377,16.35 11.377,13.848 12.358,12.867 v1(13.147,12.867)
  Bottom Layer w0.2: v1(12.475,26.25) 14.921,26.25 14.971,26.2 U1.16
SWCLK: J3.3 R2.1 U1.45 | length 10.7
  Bottom Layer w0.203: J3.3 2.023,13.234 3.003,13.234 ; R2.1 3.019,13.25 3.003,13.234 ; U1.45 7.55,18.025 6.502,16.976 6.502,16.881 5.801,16.18 4.48,16.18 3.301,15 3.003,14.703 3.003,13.234
SWDIO: J3.2 R1.2 U1.44 | length 9.4
  Layer 1 w0.203: J3.2 2.007,14.488 3.498,14.488 v1(3.505,14.495)
  Bottom Layer w0.203: v1(3.505,14.495) 3.505,14.505 4.827,15.827 6.677,15.827 6.85,16 R1.2 ; R1.2@6.855,16.055 6.855,16.83 8.05,18.025 U1.44
SWO: J3.4 U1.42 | length 12.3
  Bottom Layer w0.203: J3.4 5.216,11.941 7.423,14.148 7.423,16.773 9.05,18.4 U1.42
UART_CTS: J1.8 U1.60 | length 21.8
  Layer 1 w0.203: v1(14.6,22.05) 15.95,22.05 17,21 v1(18.25,21)
  Bottom Layer w0.203: U1.60 10.923,20.823 10.923,21.189 11.175,21.441 13.441,21.441 14,22 14.55,22 v1(14.6,22.05) ; v1(18.25,21) 19,20.25 19.9,20.25 19.905,20.255 23.045,20.255 23.05,20.25 25.79,20.25 J1.8
UART_RTS: J1.7 U1.39 | length 21.4
  Layer 1 w0.203: v1(14.6,21.4) 15.975,21.4 17.125,20.25 v1(18.25,20.25)
  Bottom Layer w0.203: U1.39 10.573,19.423 10.573,19.748 10.925,20.1 13.3,20.1 v1(14.6,21.4) ; v1(18.25,20.25) 18.328,20.25 18.681,19.897 20.046,19.897 20.051,19.902 22.899,19.902 22.904,19.897 27.719,19.897 29.343,21.52 J1.7
UART_RX: J1.6 J2.6 J3.8 U1.20 | length 64.3
  Layer 1 w0.2: v1(12.75,6.5) 12.75,5.449 13.599,4.6 21.9,4.6 22.15,4.85 v1(30.775,4.85)
  Bottom Layer w0.2: J3.8 2.139,7 10.707,7 11.207,6.5 v1(12.75,6.5) 12.75,6.419 12.85,6.319 12.85,5.125 J2.6 ; U1.20@16.05,24.193 16.607,24.193 17.225,23.575 17.225,20.568 18.248,19.545 20.192,19.545 20.196,19.55 22.754,19.55 22.758,19.545 26.085,19.545 26.651,18.98 J1.6 31,17.58 31,5.117 30.775,4.892 v1(30.775,4.85)
UART_TX: J1.5 J2.5 J3.9 U1.37 | length 54.2
  Layer 1 w0.203: v1(11.002,7.5) 10.353,8.148 10.353,13.554 10.975,14.176 10.975,17.098 v1(11.027,17.15)
  Bottom Layer w0.203: J3.9 2.909,6.5 9.25,6.5 9.252,6.502 10.708,6.502 11.002,6.208 11.002,5.418 12.463,3.956 13.381,3.956 14.125,4.7 J2.5 14.125,6.375 ; v1(11.002,7.5) 11.082,7.5 11.432,7.15 13.35,7.15 14.125,6.375 ; v1(11.027,17.15) 11.027,17.202 11.55,17.725 U1.37 ; J1.5 27.947,14.787 27.947,11.797 26.427,10.277 24.077,10.277 22.556,8.756 16.506,8.756 15.55,7.8 15.55,6.875 15.05,6.375 14.125,6.375
VCC_1V8: C4.1 C5.1 C6.1 C12.1 U3.C2 U3.C9 U3.D1 U3.D10 U3.J9 U4.5 | length 19.1
  Top Layer w0.15: v1(17.275,16.275) 17.287,16.262 17.738,16.262 U3.C9 U3.D10 ; U3.J9 18.283,12.717 18.283,12.461 v1(18.271,12.448)
  Top Layer w0.3: v1(13.3,15.9) 13.354,15.9 13.504,15.75 U3.D1 ; U3.C2 14.316,16.25 14.762,15.804 14.762,15.238 v1(14.8,15.2)
  Bottom Layer w0.3: v1(12.3,10.97) 12.338,11.008 12.771,11.008 12.8,11.038 ; U4.5 12.8,11.038 ; 12.8,11.9 12.8,11.038 ; v1(13.325,10.97) 13.287,11.008 12.829,11.008 12.8,11.038
  Bottom Layer w0.5: v1(14.8,15.2) C4.1 ; C5.1 16.6,14.05 16.6,13.666 v1(16.701,13.564) 17.436,13.564 18.271,12.729 v1(18.271,12.448) ; C6.1 16.575,16.275 v1(17.275,16.275)
  Bottom Layer w0.75: 12.8,11.9 12.25,11.9 C12.1 12.15,12.55 11.725,12.975 11.725,15.511 12.164,15.95 13.2,15.95 13.25,15.95 v1(13.3,15.9) 14.1,15.9 v1(14.8,15.2)
VCC_3V3: C7.1 C11.1 C25.1 C26.2 FB1.2 J3.1 R1.1 R3.1 R4.1 U3.J1 U3.K9 U4.6 | length 24.2
  Top Layer w0.3: v1(17.675,12.275) 17.713,12.313 17.713,12.713 U3.K9
  Top Layer w0.4: v1(13.343,13.459) 13.37,13.459 13.58,13.25 U3.J1
  Layer 1 w0.4: v1(15.484,11.716) 15.511,11.716 15.577,11.65 17.375,11.65 17.656,11.931 17.656,12.256 v1(17.675,12.275)
  Layer 1 w0.5: J3.1 2.05,15.7 3.925,15.7 4.025,15.6 5.853,15.6 5.978,15.725 7.775,15.725 v1(8.515,14.985)
  Bottom Layer w0.3: v1(17.675,12.275) 17.688,12.262 17.688,11.862 18.15,11.4 R4.1
  Bottom Layer w0.4: C7.1 12.621,13.479 13.324,13.479 v1(13.343,13.459) ; U4.6 v1(14.025,10.175) 14.75,10.9 15.6,10.9 15.506,10.994 15.506,11.667 v1@15.45,11.723 ; v1@13.4,13.5 13.975,13.5 14.725,12.75 15.072,12.75 15.122,12.7 15.241,12.7 15.475,12.466 15.475,12.05 15.469,12.044 15.469,11.731 v1(15.484,11.716) ; FB1.2 20.806,15.619 21.606,15.619 v1(21.625,15.6) ; C25.1@22.517,15.9 22.517,15.883 22.6,15.8 22.998,15.8 23.223,15.575 v1(23.25,15.575) ; C26.2 24.248,15.577 25.039,15.577 v1(25.058,15.558)
  Bottom Layer w0.5: R1.1 7.975,16.075 v1(8.55,16.075) ; R3.1 8.567,14.933 v1@8.556,14.944 ; v1(8.515,14.985) v1@8.515,16.04
VCC_EXT: C10.1 D2.1 J1.1 J2.1 J3.7 U4.1 U4.2 U4.3 | length 18.5
  Bottom Layer w0.5: J3.7 3.631,8.131 4.15,8.65 7.878,8.65 C10.1
  Bottom Layer w1: v1(20.7,5.1) 22.525,5.1 23.45,4.175 24.975,4.175 26.1,5.3 28.62,5.3 J1.1
  other v1: 20,5.1 20,5.8 20.7,5.8 14,7.4 12.6,7.652 13.3,7.652 14,8
VDD_nRF: C13.1 FB1.1 U1.14 U1.15 U1.28 | length 6
  Bottom Layer w0.25: v1(14.6,26.8) 14.707,26.693 15.154,26.693 15.161,26.7 U1.15 ; v1(14.6,27.4) 14.664,27.4 14.871,27.193 15.6,27.193 15.607,27.2 U1.14 ; v1(14.7,20.3) 14.768,20.3 14.868,20.2 U1.28
  Bottom Layer w0.5: v1(20.004,18.65) 20.55,18.65 20.675,18.775 C13.1 ; v1(20.75,18) 20.75,17.275 FB1.1
pads on no net: MT1.1 MT3.1 MT4.1 U1.1 U1.2 U1.3 U1.4 U1.5 U1.6 U1.7 U1.8 U1.9 U1.10 U1.11 U1.12 U1.21 U1.24 U1.25 U1.26 U1.27 U1.31 U1.32 U1.33 U1.34 U1.35 U1.38 U1.40 U1.41 U1.43 U1.47 U1.48 U1.49 U1.50 U1.51 U1.52 U1.53 U1.54 U1.55 U1.56 U1.57 U1.58 U1.61 U1.62 U4.7

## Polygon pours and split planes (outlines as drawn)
NetC27_1 on Bottom Layer "NETC27_1_L04_P022" (solid, pour order 22): 23.65,5.175 22.75,6.075 22.75,7.575 23.325,8.15 24.6,8.15 25.1,7.65 25.1,5.4 24.9,5.2
VCC_1V8 on Bottom Layer "VCC_1V8_L04_P010" (solid, pour order 10): 12.175,10.725 13.4,10.725 13.625,10.95 13.625,12.141 13.416,12.35 12.224,12.35 12.025,12.151 12.025,10.925 12.075,10.875 12.075,10.8
VCC_EXT on Bottom Layer "VCC_EXT_L04_P009" (solid, pour order 9): 18.9,5.9 19.2,6.2 21,6.2 21.2,6 21.2,4.2 20.9,3.9 19.1,3.9 18.9,4.1
VCC_EXT on Bottom Layer "VCC_EXT_L04_P008" (solid, pour order 8): 9.7,8.7 11.3,8.7 11.6,8.4 14.2,8.4 14.4,8.2 14.4,7.5 14.2,7.3 9.9,7.3 9.7,7.5
GND on Bottom Layer "GND_L04_P012" (solid, remove dead copper, pour order 12): 0,0 0,30 32,30 32,0
VCC_3V3 on Bottom Layer "VCC_3V3_L04_P003" (solid, pour order 3): 12.3,13.8 12.35,13.75 14.25,13.75 15,13 17.7,13 18.1,12.6 18.1,11.8 17.8,11.5 15.7,11.5 15.2,12 12.65,12 12.268,12.382 12.268,12.412
GND on Layer 2 "GND_L03_P021" (solid, pour order 21): 0,0 0,30 32,30 32,0
VCC_3V3 on Layer 2 "VCC_3V3_L03_P020" (solid, pour order 20): 5.414,13.675 9.039,17.3 24.5,17.3 25.2,16.6 25.2,9.014 24.886,8.7 6.8,8.7 5.4,10.1
VCC_EXT on Layer 2 "VCC_EXT_L03_P006" (solid, pour order 6): 15.45,8.2 17.55,6.1 21.1,6.1 21.2,6 21.2,4.8 21,4.6 18.5,4.6 18.2,4.9 16,4.9 14.1,6.8 12.1,6.8 12,6.9 12,8.1 12.1,8.2
VDD_nRF on Layer 1 "NONET_L-01_P-001" (solid, pour order 5): 12.7,19.1 14.535,17.265 20.378,17.265 21.05,17.937 21.05,19.65 19.6,21.1 14.922,21.1 14.4,21.622 14.4,24.3 15.3,25.2 15.3,27.6 14.7,28.2 12.9,28.2 12.7,28
NetC27_1 on Layer 1 "NETC27_1_L02_P023" (solid, pour order 23): 22.8,7.1 22.814,7.114 22.814,9.014 25.2,11.4 25.2,16.8 23.5,18.5 23.5,22.1 22.52,23.08 22.52,25.12 23,25.6 25.6,25.6 26.1,25.1 26.1,22 27.1,21 27.1,7.6 25.35,5.85 23.35,5.85 22.8,6.4
VCC_3V3 on Layer 1 "VCC_3V3_L02_P015" (solid, pour order 15): 13.5,10.4 13.5,11.2 14.259,11.2 15.38,12.32 18.863,12.32 20.131,13.589 20.131,16.531 20.8,17.2 24.392,17.2 24.875,16.675 24.875,11.706 23.575,10.406 22.369,9.2 13.8,9.2 13.5,9.5
VCC_1V8 on Layer 1 "VCC_1V8_L02_P013" (solid, pour order 13): 14.775,16.525 14.95,16.7 17.225,16.7 17.475,16.45 17.475,13.825 16.9,13.25 15.024,13.25 12.975,15.299 12.975,16.35 13.175,16.55
GND on Layer 1 "GND_L02_P024" (solid, pour order 24): 0,0 0,30 32,30 32,0
GND on Top Layer "GND_L01_P016" (solid, remove dead copper, pour order 16): 0,0 0,30 32,30 32,0

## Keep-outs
Keep-Out Layer:
  the board outline again, w0.1

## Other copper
Multi-Layer:
  pour cut-out: 0.1,17.3 5.7,17.3 5.7,29.9 0.1,29.9 0.1,17.8

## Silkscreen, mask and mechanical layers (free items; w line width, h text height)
Top Overlay:
  drawing of 3543 lines, arcs and shapes, not listed
  text "AS-611B _n" at 0.822,23.671 h1
  text "202404" at 1.524,22.31 h1
Bottom Overlay:
  text "RX" at 13.075,6.386 h0.7 r270
  text "TX" at 13.975,6.275 h0.7 r270
  text "NRST" at 15.207,6.25 h0.7 r270
  text "GND" at 17.507,6.25 h0.7 r270
  text "VCC" at 18.782,6.151 h0.7 r270
  text "GPIO_EXT" at 16.377,6.1 h0.7 r270
Dimensions:
  text "Layer : 4L" at 10.1,40.558 h3
  text "Thickiness : 1.0mm" at 9.9,37.031 h3

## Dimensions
32,30 to 32,0 on Dimensions
0,30 to 32,30 on Dimensions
